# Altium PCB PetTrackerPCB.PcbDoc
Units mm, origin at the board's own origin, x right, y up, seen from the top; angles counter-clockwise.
Board outline 116.71 x 58.42 mm, 4 copper layers (Top Layer, GND Plane, PWR Plane, Bottom Layer), stack 0.868 mm thick; 37 components, 41 nets, 216 pads, 92 vias.
Unrouted connection lines stored in the file: 63.
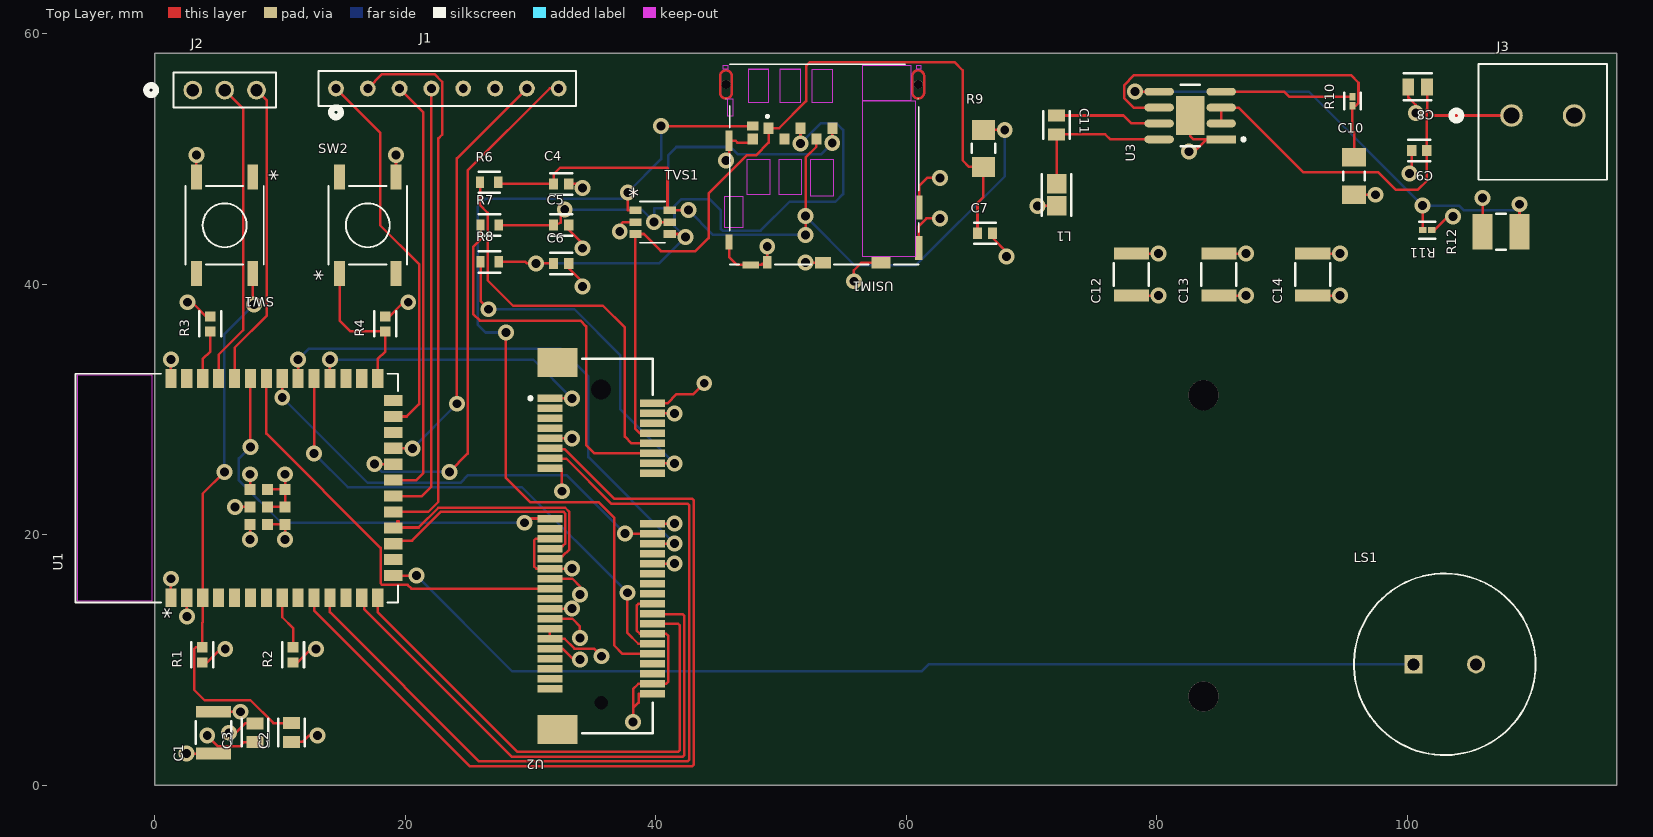
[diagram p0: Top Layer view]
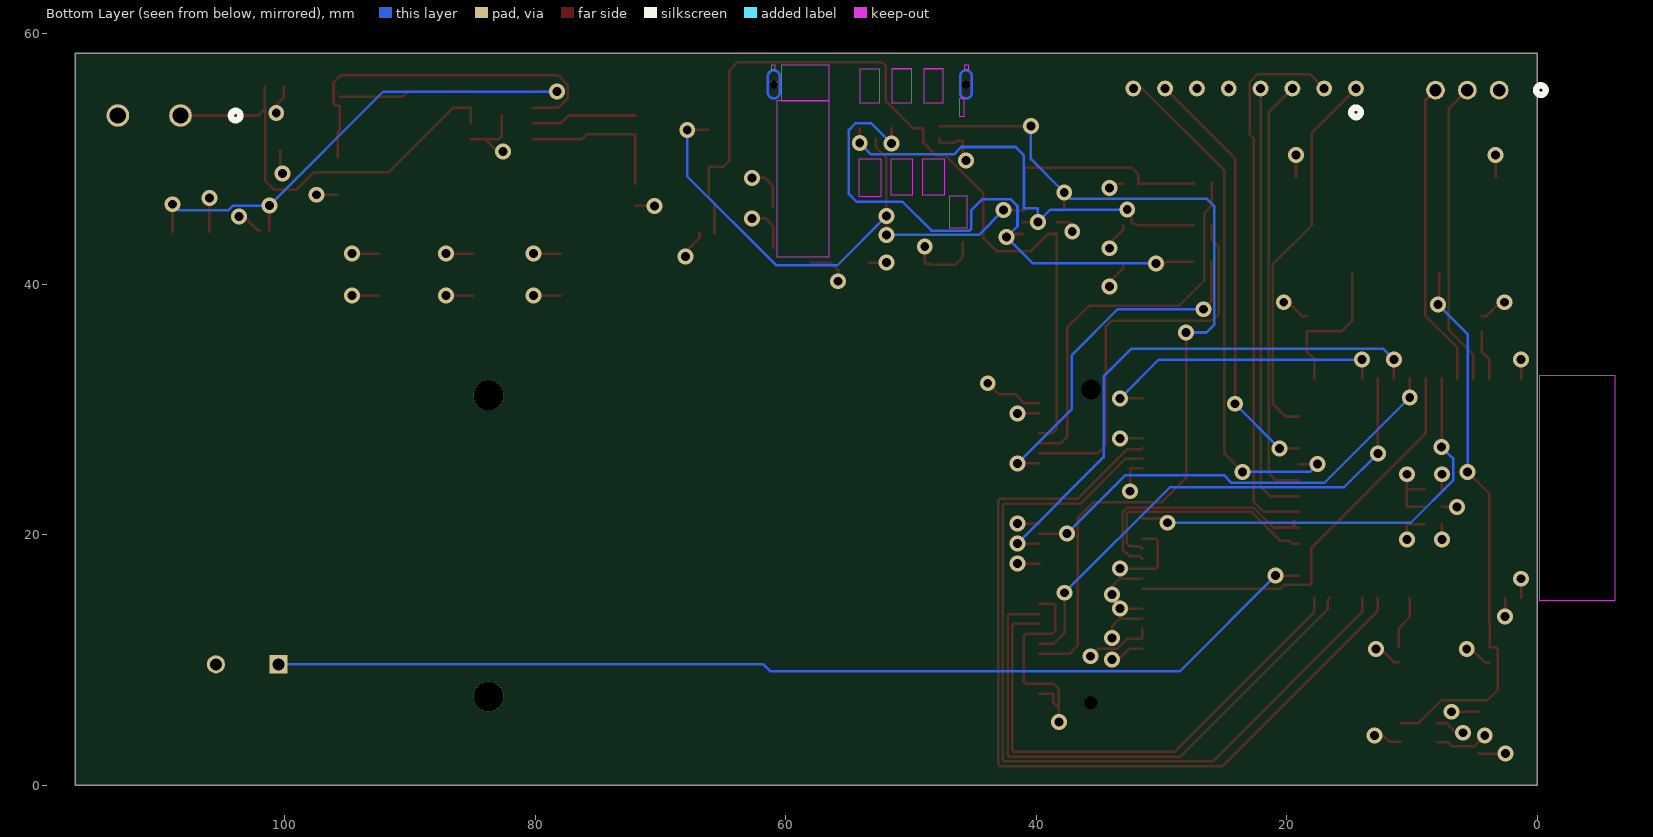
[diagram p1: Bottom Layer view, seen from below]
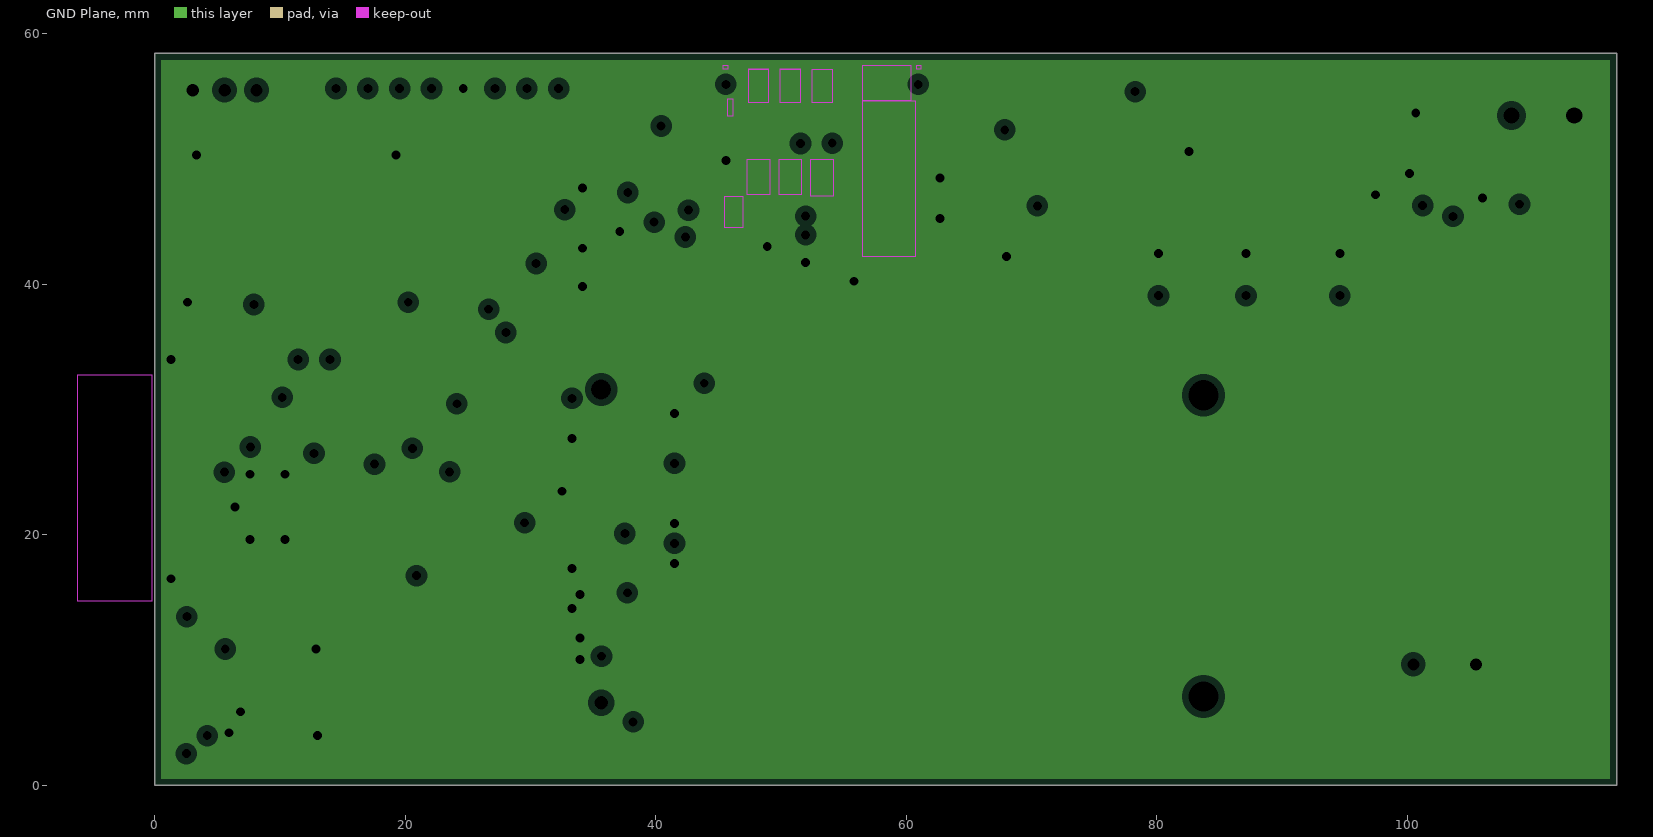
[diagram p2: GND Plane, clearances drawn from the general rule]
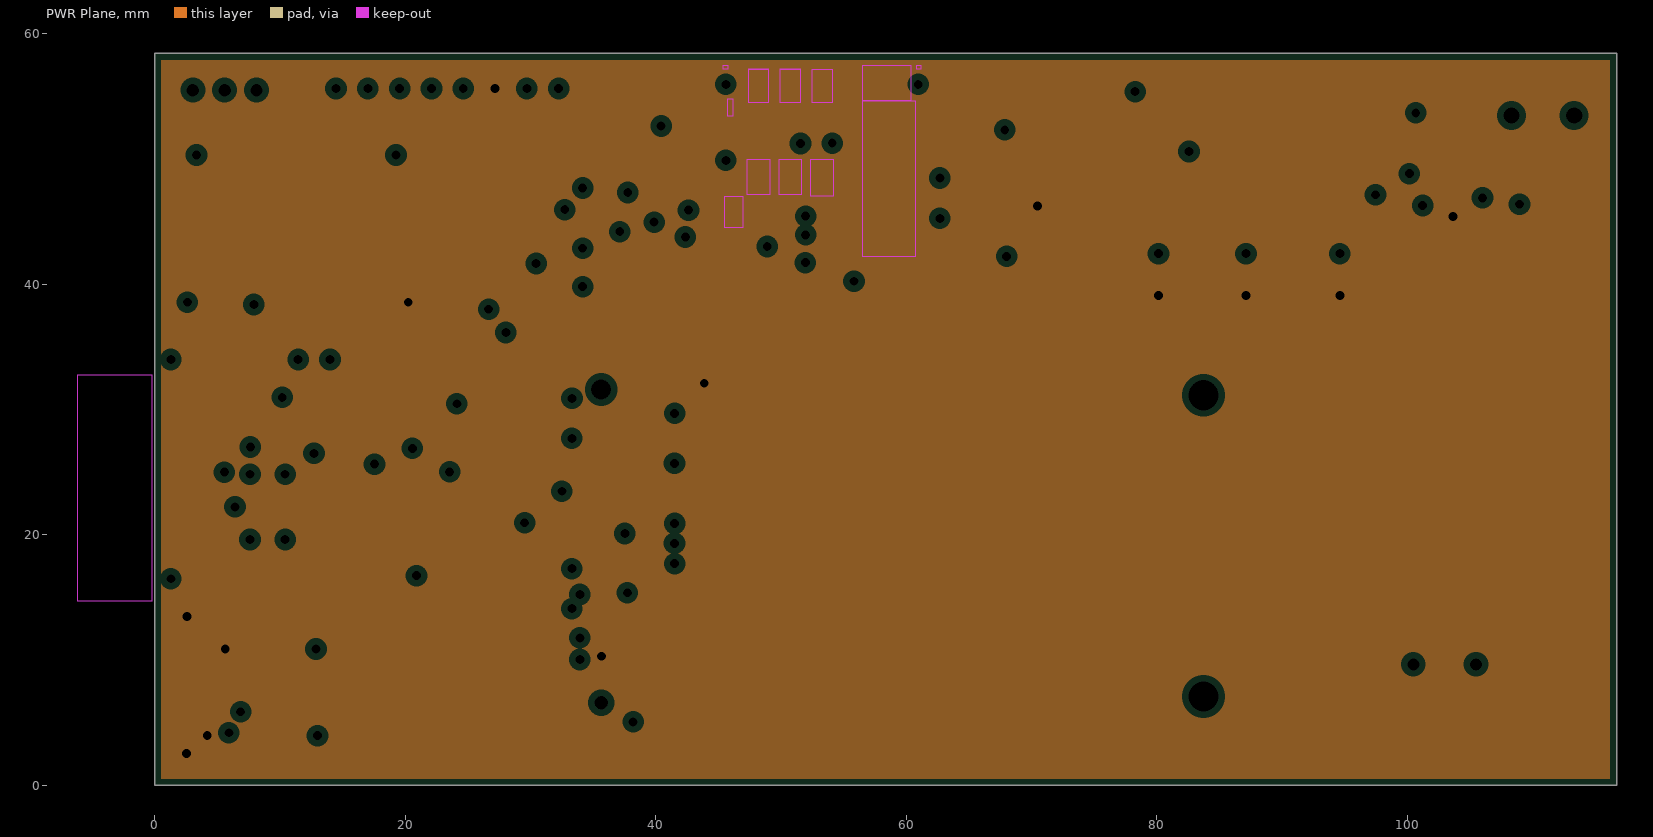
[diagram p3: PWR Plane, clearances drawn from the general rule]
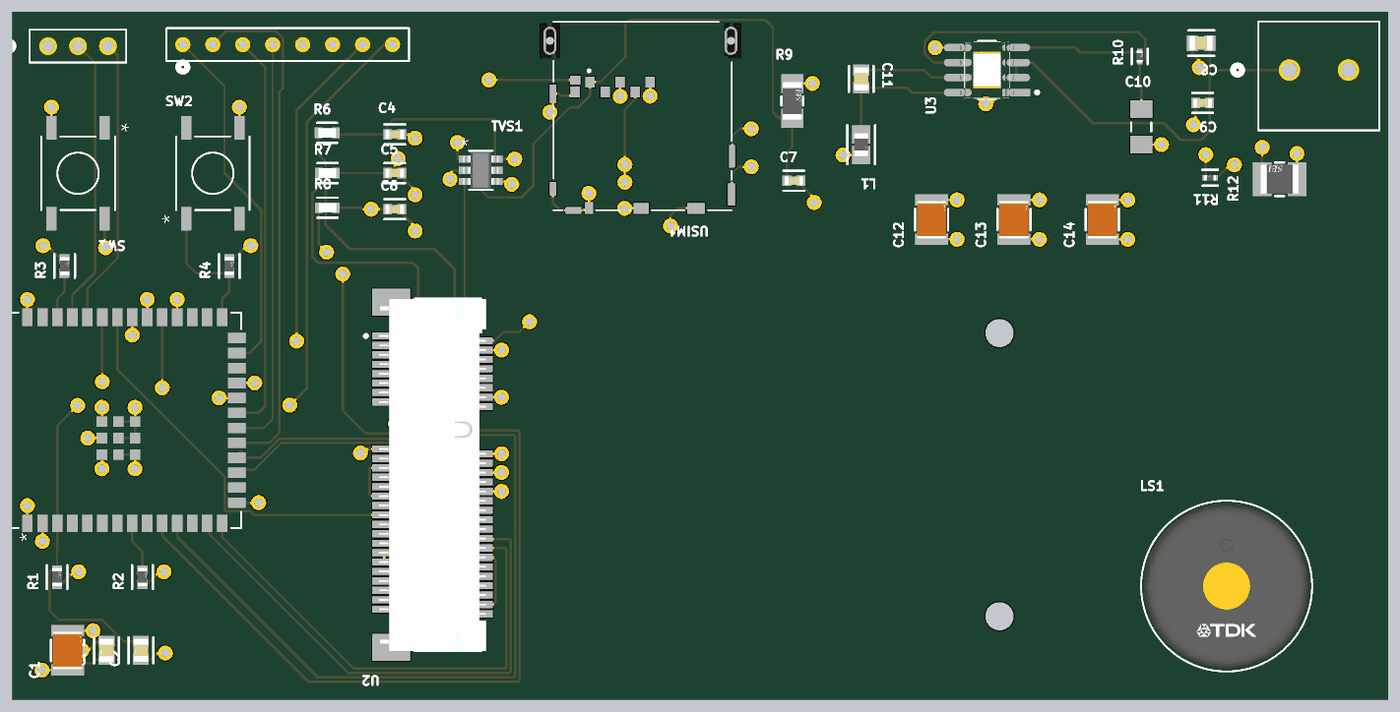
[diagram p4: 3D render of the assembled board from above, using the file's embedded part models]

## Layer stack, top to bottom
Top Solder: solder mask 0.0102, Solder Resist, Dk 3.5
Top Layer: signal copper 0.0356
Dielectric 4: core 0.1016, Core-009, Dk 4.5
Dielectric 2: core 0.1016, Core-009, Dk 4.5
GND Plane: plane copper 0.035, net GND
Dielectric 1: dielectric 0.32, FR-4, Dk 4.8
PWR Plane: plane copper 0.035, net +3V3
Dielectric 3: core 0.1016, Core-009, Dk 4.5
Dielectric 5: core 0.1016, Core-009, Dk 4.5
Bottom Layer: signal copper 0.0356
Bottom Solder: solder mask 0.0102, Solder Resist, Dk 3.5

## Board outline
0,0 116.713,0 116.713,58.42 0,58.42

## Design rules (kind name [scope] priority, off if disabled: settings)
Clearance [All] p1: gap=0.127 ignorepadtopadclearanceinfootprint=FALSE
Height [All] p1 off: minheight=0 maxheight=25.4 prefheight=12.7
PlaneClearance [All] p1: clearance=0.508
PlaneConnect [All] p1: planeconnectstyle=Relief reliefexpansion=0.508 reliefentries=4 reliefconductorwidth=0.254 reliefairgap=0.254
PolygonConnect [All] p1: connectstyle=Relief reliefconductorwidth=0.254 reliefentries=4 polygonreliefangle="90 Angle" airgapwidth=0.254
RoutingVias [All] p1: holewidth=0.711 width=1.27 viastyle="Through Hole" minholewidth=0.711 minwidth=1.27 maxholewidth=0.711 maxwidth=1.27
SolderMaskExpansion [All] p1: expansion=0.102 istentingtop=FALSE
SupplyNets "Schematic Supply Nets_2" [InNet('GND')] p1: voltage=0.000
SupplyNets "Schematic Supply Nets_1" [InNet('Vin')] p2: voltage=0.000
SupplyNets "Schematic Supply Nets" [InNet('+3V3')] p3: voltage=0.000
Width [All] p1: maxlimit=25.4 minlimit=0.127 preferedwidth=0.203
27 further rules are at their usual default settings.

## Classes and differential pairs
component class PowerSupply: C8 C9 C10 C11 C12 C13 C14 CBOOT CHF CIN Cout CVCC J3 L L1 R10 R11 R12 RFBB RFBT U3
component class EC25: C4 C5 C6 C7 CRF1 CRF2 CRF3 CRF4 R6 R7 R8 R9 RDB1 RDB2 RDB3 RS1 TVS1 "TVS Array" U2 USIM1 "USIM Connector"
component class Dataflow: C1 C2 C3 "Camera Interface" J1 J2 LS1 R1 R2 R3 R4 RDB RPU1 S2 SW1 SW2 U1 "USB Connector"

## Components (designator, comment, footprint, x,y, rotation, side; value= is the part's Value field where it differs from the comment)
C1 "22uF" FP-C3225-250-0_4-IPC_B 4.699,4.191 r90 top
C2 "0.1uF" FP-C0805C104M5UACTU-MFG 10.922,4.203 r90 top
C3 "0.1uF" FP-C0805C104M5UACTU-MFG 8.001,4.191 r90 top
C4 "0.1uF" FP-C0603C-CF-MFG 32.447,48.006 r0 top value="0.10 μF"
C5 "0.1uF" FP-C0603C-CF-MFG 32.447,44.72 r0 top value="0.10 μF"
C6 "0.1uF" FP-C0603C-CF-MFG 32.447,41.656 r0 top value="0.10 μF"
C7 "0.1uF" FP-C0603C-CF-MFG 66.294,44.069 r0 top value="0.10 μF"
C8 "10uF" FP-C0805C-DG-MFG 100.838,55.753 r180 top
C9 "0.22uF" FP-C0603C-CF-MFG 100.965,50.673 r180 top value="0.22 μF"
C10 "1uF" CAPC3216X180X50ML20T25 95.758,48.641 r90 top
C11 "0.1uF" FP-C0805C104M5UACTU-MFG 72.009,52.717 r270 top
C12 "22uF" FP-C3225-250-0_4-IPC_B 77.978,40.767 r90 top
C13 "22uF" FP-C3225-250-0_4-IPC_B 84.963,40.767 r90 top
C14 "22uF" FP-C3225-250-0_4-IPC_B 92.456,40.767 r90 top
J1 "TS-108-T-A" CON8_1X8_TU_HTS_SAI 23.368,55.626 r0 top
J2 "PREC003SAAN-RC" CONN_PREC003SAAN-RC_SUL 3.048,55.499 r0 top
J3 "1935161" CONN_1935161_PXC 108.331,53.467 r0 top value=10uF
L1 "6.8uH" FP-MLZ2012-0_85-IPC_A 72.009,47.13 r270 top
LS1 "PS1440P02BT" FP-PS1440P02BT-MFG 102.997,9.652 r0 top
R1 "10kΩ" FP-RMCF0603-IPC_C 3.81,10.414 r90 top
R2 "10kΩ" FP-RMCF0603-IPC_C 11.049,10.414 r90 top
R3 "10kΩ" FP-RMCF0603-IPC_C 4.445,36.83 r90 top
R4 "10kΩ" FP-RMCF0603-IPC_C 18.415,36.83 r90 top
R6 "0Ω" FP-RMCF0603-MFG 26.707,48.133 r0 top value=0mΩ
R7 "0Ω" FP-RMCF0603-MFG 26.744,44.718 r0 top value=0mΩ
R8 "0Ω" FP-RMCF0603-MFG 26.744,41.783 r0 top value=0mΩ
R9 "15kΩ" FP-RMCF1206-IPC_A 66.167,50.848 r90 top
R10 "100kΩ" FP-RMCF0402-IPC_C 95.631,54.61 r90 top
R11 "100kΩ" FP-RMCF0402-IPC_C 101.6,44.323 r180 top
R12 "3.3kΩ" FP-RMCF1210-IPC_A 107.49,44.196 r180 top
SW1 "PTS645SL43SMTR92LFS" PTS645SL43SMTR92LFS_CNK 5.588,44.704 r270 top
SW2 "PTS645SL43SMTR92LFS" PTS645SL43SMTR92LFS_CNK 17.018,44.704 r90 top
TVS1 "AQRV05-4HTG" SOT23-6_LTF 39.751,44.958 r0 top
U1 "ESP32-S2-SOLO-N4R2" MOD41_ESP32-S2-SOLO_EXP 6.557,23.722 r90 top
U2 "2041119-1" TECO-2041119-1_3_V 35.651,19.092 r270 top
U3 "LMR33640ADDAR" FP-DDA0008J-IPC_A 82.677,53.467 r180 top
USIM1 "2174803-2" CONN_2174803-2 50.927,51.151 r180 top

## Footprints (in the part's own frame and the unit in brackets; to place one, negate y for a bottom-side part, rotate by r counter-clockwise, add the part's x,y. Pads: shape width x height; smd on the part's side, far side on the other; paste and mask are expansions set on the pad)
CAPC3216X180X50ML20T25 [mm] "Chip Capacitor, 2-Leads, Body 3.40x1.80mm, IPC Low Density"
  rect 1.5x1.9 smd: 1(-1.5,0) 2(1.5,0)
  silkscreen extent -0.35,-0.85 0.35,0.85, body extent -1.7,-0.9 1.7,0.9, height 1.8
CON8_1X8_TU_HTS_SAI [mil]
  round 50 / inner round 60 / far side round 50 hole 28 paste-99999 mask+0: 1(-350,0) 2(-250,0) 3(-150,0) 4(-50,0) 5(50,0) 6(150,0) 7(250,0) 8(350,0)
  silkscreen extent -405,-90 405,55
CONN_1935161_PXC [mil]
  round 71 / inner round 60 / far side round 71 hole 51 paste-99999 mask+0: 1(0,0) 2(196.85,0)
  silkscreen extent -188,-202 300,162
CONN_2174803-2 [mm]
  rect 0.8x0.9 smd: C1(1.905,-1.3) C2(-0.635,-1.3) C3(-3.175,-1.3) C5(3.175,-0.45) C6(0.635,-0.45) C7(-1.905,-0.45)
  rect 0.1x0.1 smd paste-1 mask+0: C8(5.315,-3.657) C17(-10.035,-3.657)
  rect 0.54x1.6 smd: C9(5.065,-0.3)
  rect 0.54x1.17 smd: C10(5.065,7.785)
  rect 1.33x0.55 smd: C11(3.33,9.605)
  rect 0.7x0.98 smd: C12(2.015,9.39)
  rect 1.3x0.91 smd: C13(-2.435,9.425)
  rect 1.53x0.91 smd: C14(-7.07,9.425)
  rect 0.6x1.9 smd: C15(-10.085,8.25)
  rect 0.5x1.9 smd: C16(-10.135,5.02)
  rect 0.9x0.75 smd: SW(3.175,-1.475)
  round 0.7 hole 0.7 unplated: ""(-10.035,-4.8) ""(5.315,-4.8)
  Top Layer region: 123 vertices and 1 holes, not listed, extent 4.765,-6 5.865,-3.6
  Top Layer region: 124 vertices and 1 holes, not listed, extent -10.585,-6 -9.485,-3.6
  Bottom Layer region: 123 vertices and 1 holes, not listed, extent 4.765,-6 5.865,-3.6
  Bottom Layer region: 124 vertices and 1 holes, not listed, extent -10.585,-6 -9.485,-3.6
  Keep-Out Layer region: -5.624,-3.502 -9.806,-3.502 -9.806,8.97 -5.624,8.97
  Keep-Out Layer region: -5.624,-6.326 -9.458,-6.326 -9.458,-3.5 -5.624,-3.5
  Keep-Out Layer region: -1.565,-6.021 -3.155,-6.021 -3.155,-3.35 -1.565,-3.35
  Keep-Out Layer region: 0.975,-6.024 -0.615,-6.024 -0.615,-3.35 0.975,-3.35
  Keep-Out Layer region: 3.515,-6.031 1.928,-6.031 1.928,-3.35 3.515,-3.35
  Keep-Out Layer region: 5.515,-6.332 5.175,-6.332 5.175,-6.02 5.515,-6.02
  Keep-Out Layer region: 5.165,-3.65 4.765,-3.65 4.765,-2.25 5.165,-2.25
  Keep-Out Layer region: -1.465,1.172 -3.261,1.172 -3.261,4.12 -1.465,4.12
  Keep-Out Layer region: 1.075,1.171 -0.716,1.171 -0.716,4 1.075,4
  Keep-Out Layer region: 3.615,1.172 1.828,1.172 1.828,4 3.615,4
  Keep-Out Layer region: 5.42,4.127 3.977,4.127 3.977,6.63 5.42,6.63
  Keep-Out Layer region: -9.9,-6.323 -10.24,-6.323 -10.24,-6.02 -9.9,-6.02
  Keep-Out Layer region: -5.624,-3.505 -9.815,-3.505 -9.815,8.97 -5.624,8.97
  Keep-Out Layer region: -5.624,-6.322 -9.452,-6.322 -9.452,-3.5 -5.624,-3.5
  Keep-Out Layer region: -1.565,-6.027 -3.159,-6.027 -3.159,-3.35 -1.565,-3.35
  Keep-Out Layer region: 0.975,-6.023 -0.615,-6.023 -0.615,-3.35 0.975,-3.35
  Keep-Out Layer region: 3.515,-6.021 1.925,-6.021 1.925,-3.35 3.515,-3.35
  Keep-Out Layer region: 5.515,-6.326 5.17,-6.326 5.17,-6.02 5.515,-6.02
  Keep-Out Layer region: 5.165,-3.653 4.768,-3.653 4.768,-2.25 5.165,-2.25
  Keep-Out Layer region: -1.465,1.172 -3.261,1.172 -3.261,4.12 -1.465,4.12
  Keep-Out Layer region: 1.075,1.171 -0.716,1.171 -0.716,4 1.075,4
  Keep-Out Layer region: 3.615,1.171 1.826,1.171 1.826,4 3.615,4
  Keep-Out Layer region: 5.42,4.123 3.973,4.123 3.973,6.63 5.42,6.63
  Keep-Out Layer region: -9.9,-6.332 -10.255,-6.332 -10.255,-6.02 -9.9,-6.02
  Keep-Out Layer region: -5.624,-3.506 -9.818,-3.506 -9.818,8.97 -5.624,8.97
  Keep-Out Layer region: -5.624,-6.322 -9.454,-6.322 -9.454,-3.5 -5.624,-3.5
  Keep-Out Layer region: -1.565,-6.024 -3.157,-6.024 -3.157,-3.35 -1.565,-3.35
  Keep-Out Layer region: 0.975,-6.03 -0.616,-6.03 -0.616,-3.35 0.975,-3.35
  Keep-Out Layer region: 3.515,-6.028 1.927,-6.028 1.927,-3.35 3.515,-3.35
  Keep-Out Layer region: 5.515,-6.332 5.175,-6.332 5.175,-6.02 5.515,-6.02
  Keep-Out Layer region: 5.165,-3.653 4.769,-3.653 4.769,-2.25 5.165,-2.25
  Keep-Out Layer region: -1.465,1.172 -3.261,1.172 -3.261,4.12 -1.465,4.12
  Keep-Out Layer region: 1.075,1.171 -0.715,1.171 -0.715,4 1.075,4
  Keep-Out Layer region: 3.615,1.17 1.825,1.17 1.825,4 3.615,4
  Keep-Out Layer region: 5.42,4.121 3.971,4.121 3.971,6.63 5.42,6.63
  Keep-Out Layer region: -9.9,-6.332 -10.255,-6.332 -10.255,-6.02 -9.9,-6.02
  silkscreen extent -10.09,-6.4 5.01,9.58
CONN_PREC003SAAN-RC_SUL [mil]
  round 59 / inner round 60 / far side round 59 hole 39 paste-99999 mask+0: 1(0,0) 2(100,0) 3(200,0)
  silkscreen extent -146,-55 261,55
FP-C0603C-CF-MFG [mm]
  rect 0.75x0.9 smd paste+0 mask+0: 1(-0.6,0) 2(0.6,0)
  silkscreen extent -0.88,-0.85 0.88,0.85, body extent -1.2,-0.6 1.2,0.6, height 0.25
FP-C0805C104M5UACTU-MFG [mm]
  rect 0.95x1.35 smd paste+0 mask+0: 1(-0.75,0) 2(0.75,0)
  silkscreen extent -1.1,-1.05 1.1,1.05, body extent -1.4,-0.85 1.4,0.85, height 0.25
FP-C0805C-DG-MFG [mm]
  rect 0.95x1.35 smd paste+0 mask+0: 1(-0.75,0) 2(0.75,0)
  silkscreen extent -1.11,-1.08 1.1,1.07, body extent -1.4,-0.85 1.4,0.85, height 0.25
FP-C3225-250-0_4-IPC_B [mm]
  rect 0.953x2.804 smd paste+0 mask+0: 1(-1.675,0) 2(1.675,0)
  silkscreen extent -0.9,-1.4 0.9,1.4, body extent -2.4,-1.65 2.4,1.65, height 0.25
FP-DDA0008J-IPC_A [mm]
  rect 2.353x0.622 smd paste+0 mask+0: 1(-2.477,1.905)
  rrect100% 2.353x0.622 smd paste+0 mask+0: 2(-2.477,0.635) 3(-2.477,-0.635) 4(-2.477,-1.905) 5(2.477,-1.905) 6(2.477,-0.635) 7(2.477,0.635) 8(2.477,1.905)
  rect 2.3x3.1 smd paste-1000 mask+0: 9(0,0)
  silkscreen extent -4.38,-2.45 0.75,2.45, body extent -4.15,-2.95 4.15,2.95, height 0.25
FP-MLZ2012-0_85-IPC_A [mm]
  rect 1.554x1.556 smd paste+0 mask+0: 1(-0.876,0) 2(0.876,0)
  silkscreen extent -1.65,-1.18 1.65,1.18, body extent -2.15,-1.28 2.15,1.28, height 0.25
FP-PS1440P02BT-MFG [mm]
  rect 1.45x1.45 hole 0.95 paste-2539.97 mask+0: 1(-2.5,0)
  round 1.45 hole 0.95 paste-2539.97 mask+0: 2(2.5,0)
  silkscreen extent -7.25,-7.25 7.25,7.25, body extent -7.35,-7.35 7.35,7.35, height 0.25
FP-RMCF0402-IPC_C [mm]
  rect 0.581x0.472 smd paste+0 mask+0: 1(-0.366,0) 2(0.366,0)
  silkscreen extent -0.66,-0.67 0.66,0.67, body extent -0.76,-0.38 0.76,0.38, height 0.25
FP-RMCF0603-IPC_C [mm]
  rect 0.806x0.858 smd paste+0 mask+0: 1(-0.601,0) 2(0.601,0)
  silkscreen extent -1,-0.87 1,0.87, body extent -1.1,-0.58 1.1,0.58, height 0.25
FP-RMCF0603-MFG [mm]
  rect 0.65x0.9 smd paste+0 mask+0: 1(-0.725,0) 2(0.725,0)
  silkscreen extent -0.85,-0.85 0.85,0.85, body extent -1.15,-0.58 1.15,0.58, height 0.25
FP-RMCF1206-IPC_A [mm]
  rect 1.604x1.858 smd paste+0 mask+0: 1(-1.476,0) 2(1.476,0)
  silkscreen extent -0.37,-0.93 0.37,0.93, body extent -2.78,-1.43 2.78,1.43, height 0.25
FP-RMCF1210-IPC_A [mm]
  rect 1.604x2.855 smd paste+0 mask+0: 1(-1.476,0) 2(1.476,0)
  silkscreen extent -0.37,-1.43 0.37,1.43, body extent -2.78,-1.93 2.78,1.93, height 0.25
MOD41_ESP32-S2-SOLO_EXP [mil]
  rect 59x35 smd paste+0 mask+0: 1(-344.49,207.09) 2(-344.49,157.09) 3(-344.49,107.09) 4(-344.49,57.09) 5(-344.49,7.09) 6(-344.49,-42.91) 7(-344.49,-92.91) 8(-344.49,-142.91) 9(-344.49,-192.91) 10(-344.49,-242.91) 11(-344.49,-292.91) 12(-344.49,-342.91) 13(-344.49,-392.91) 14(-344.49,-442.91) 27(344.49,-442.91) 28(344.49,-392.91) 29(344.49,-342.91) 30(344.49,-292.91) 31(344.49,-242.91) 32(344.49,-192.91) 33(344.49,-142.91) 34(344.49,-92.91) 35(344.49,-42.91) 36(344.49,7.09) 37(344.49,57.09) 38(344.49,107.09) 39(344.49,157.09) 40(344.49,207.09)
  rect 35x59 smd paste+0 mask+0: 15(-275,-492.13) 16(-225,-492.13) 17(-175,-492.13) 18(-125,-492.13) 19(-75,-492.13) 20(-25,-492.13) 21(25,-492.13) 22(75,-492.13) 23(125,-492.13) 24(175,-492.13) 25(225,-492.13) 26(275,-492.13)
  rect 35x35 smd paste+0 mask+0: 41(-59.05,-96.85) 42(-114.17,-41.73) 43(-114.17,-96.85) 44(-114.17,-151.97) 45(-59.05,-151.97) 46(-3.94,-151.97) 47(-3.94,-96.85) 48(-3.94,-41.73) 49(-59.05,-41.73)
  Keep-Out Layer region: 354.5,502 -354.5,502 -354.5,266 354.5,266
  silkscreen extent -359,-507 360,507
PTS645SL43SMTR92LFS_CNK [mil]
  rect 79x34 smd paste+0 mask+0: 1(-151.5,88.58) 2(151.5,88.58) 3(-151.5,-88.58) 4(151.5,-88.58)
  silkscreen extent -123,-123 123,123
SOT23-6_LTF [mil]
  rect 38.5x24 smd paste+0 mask+0: 1(-53.75,37.4) 2(-53.75,0) 3(-53.75,-37.4) 4(53.75,-37.4) 5(53.75,0) 6(53.75,37.4)
  silkscreen extent -40,-65 40,65, body extent -59,-60 59,60, height 57
TECO-2041119-1_3_V [mm] "Connector, 52-Leads, Body 29.9x8.2mm, Pitch 0.4mm"
  rect 0.6x2 smd: 1(-11.8,-4.1) 2(-11.4,4.1) 3(-11,-4.1) 4(-10.6,4.1) 5(-10.2,-4.1) 6(-9.8,4.1) 7(-9.4,-4.1) 8(-9,4.1) 9(-8.6,-4.1) 10(-8.2,4.1) 11(-7.8,-4.1) 12(-7.4,4.1) 13(-7,-4.1) 14(-6.6,4.1) 15(-6.2,-4.1) 16(-5.8,4.1) 17(-2.2,-4.1) 18(-1.8,4.1) 19(-1.4,-4.1) 20(-1,4.1) 21(-0.6,-4.1) 22(-0.2,4.1) 23(0.2,-4.1) 24(0.6,4.1) 25(1,-4.1) 26(1.4,4.1) 27(1.8,-4.1) 28(2.2,4.1) 29(2.6,-4.1) 30(3,4.1) 31(3.4,-4.1) 32(3.8,4.1) 33(4.2,-4.1) 34(4.6,4.1) 35(5,-4.1) 36(5.4,4.1) 37(5.8,-4.1) 38(6.2,4.1) 39(6.6,-4.1) 40(7,4.1) 41(7.4,-4.1) 42(7.8,4.1) 43(8.2,-4.1) 44(8.6,4.1) 45(9,-4.1) 46(9.4,4.1) 47(9.8,-4.1) 48(10.2,4.1) 49(10.6,-4.1) 50(11,4.1) 51(11.4,-4.1) 52(11.8,4.1)
  round 1.3 hole 1.6 unplated: MH1(-12.5,0)
  round 0.9 hole 1.1 unplated: MH2(12.5,0)
  rect 2.3x3.2 smd: MP1(-14.65,-3.5) MP2(14.65,-3.5)
  silkscreen extent -14.95,-5.77 14.95,4.1, body extent -14.95,-4.54 14.95,4.55, height 4

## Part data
C1 C12 C13 C14: library part CMP-2000-06052-2, "C3225X7R1C226M250AC Multilayer Ceramic Capacitors 22uF ±20% 16V X7R SMD 1210", Case Code (Imperial)=1210, Case Code (Metric)=3225, Dielectric=X7R, Dielectric Material=Ceramic, Max Operating Temperature=125°C, Min Operating Temperature=-55°C, Package Quantity=1, Tolerance=20%, Voltage Rating=16V
C2 C3 C11: library part CMP-2007-03742-2, "C0805C104M5UACTU CAP CER 0.1UF 50V Z5U 0805", Capacitance=100nF, Case Code (Imperial)=0805, Case Code (Metric)=2012, Dielectric=Z5U, Dielectric Material=Ceramic, Max Operating Temperature=85°C, Min Operating Temperature=10°C, Package Quantity=1, Tolerance=20%, Voltage=50V
C4 C5 C6 C7: library part CMP-2006-03056-2, "C0603C104J5RACTU CAP CER 0.1UF 50V 5% X7R 0603", Capacitance="0.10 μF", Manufacturer=KEMET, Manufacturer Part Number=C0603C104J5RACTU, Package=C0603C-CF, Temperature="-55°C to +125°C", Temperature Characteristic=X7R, Temperature Coefficient=30ppm/°C, Temperature Range High=+125°C, Temperature Range Low=-55°C, Tolerance=0.05, Voltage Rating="50 V"
C8: library part CMP-2007-03243-2, "C0805C106K8PACTU CAP CER 10UF 10V X5R 0805", 3DS Part Number=220-00001, Manufacturer=Kemet, Manufacturer Part Number=C0805C106K8PACTU, Package=C0805C-DG, Temperature="-55°C to +85°C", Temperature Characteristic=X5R, Temperature Coefficient=15%, Temperature Range High=+85°C, Temperature Range Low=-55°C, Tolerance=10%, Voltage=10V
C9: library part CMP-2006-03146-2, "C0603C224K3RACTU CAP CER 0.22UF 25V 10% X7R 0603", Capacitance="0.22 μF", Manufacturer=KEMET, Manufacturer Part Number=C0603C224K3RACTU, Package=C0603C-CF, Temperature="-55°C to +125°C", Temperature Characteristic=X7R, Temperature Coefficient=30ppm/°C, Temperature Range High=+125°C, Temperature Range Low=-55°C, Tolerance=0.1, Voltage Rating="25 V"
C10: library part CMP-2000-04991-1, "C1206C105K3RACTU Chip Capacitor, 1 uF, +/- 10%, 25 V, -55 to 125 degC, 1206 (3216 Metric), RoHS, Tape and Reel", Capacitance - nF=1000nF, Case Code - in=1206, Case Code - mm=3216, Case Height=1.6mm, Case Length=3.2mm, Dielectric=X7R, Manufacturer=Kemet, Maximum Operating Temperature=+125C, Minimum Operating Temperature=-55C, Operating Temperature Range=-55Cto+125C, Package / Case=1206(3216metric), Package Description="2-Pin Surface Mount Device, Body 3.2 x 1.6 mm", Temperature Coefficient / Code=+/-15%, Tolerance=10%, Voltage Rating=25V
J1: "No Description Available", Mfr_Name="Samtec Inc"
J2: "No Description Available", Mfr_Name=Sullins
J3: "Ceramic Capacitor, Multilayer, Ceramic, 16V, 10% +Tol, 10% -Tol, X5R, 15% TC, 10uF, Surface Mount, 0805", Capacitor Type=Ceramic, Case/Package=0805, Manufacturer=Samsung, Manufacturer Part Number=CL21A106KOQNNNE, Max Operating Temperature=85°C, Mfr_Name="Phoenix Contact", Min Operating Temperature=-55°C, Package Shape=Rectangular, Package Style=SMTMeter, Rated DC Voltage (URdc)=16V, Supplier Part Number=1276-1096-1-ND, Temperature Characteristics Code=X5R, Tolerance  (fill in as +-)=10%
L1: library part CMP-08253-000092-1, "MLZ2012N6R8LT000 Shielded Multilayer Inductor 6.8uH ±20% 550mA 325mΩ SMD 0805", Case Code (Imperial)=0805, Case Code (Metric)=2012, Current Rating=550mA, DC Resistance (DCR)=250mR, Max Operating Temperature=125°C, Min Operating Temperature=-55°C, Package Quantity=1, Saturation Current=110mA, Self Resonant Frequency=60MHz, Test Frequency=2MHz, Tolerance=20%
LS1: library part CMP-08413-000003-1, "AUDIO PIEZO TRANSDUCER 30V TH", Frequency=4kHz, Max Operating Temperature=70°C, Min Operating Temperature=-10°C, Operating Supply Voltage=3V, Package Quantity=350
R1 R2 R3 R4: library part CMP-26527-002098-1, "RMCF0603JT10K0 10kΩ ±5% 0.1W 0603 Thick Film Chip Resistor AEC-Q200 compliant", Case Code (Imperial)=0603, Case Code (Metric)=1608, Max Operating Temperature=155°C, Max Power Dissipation=100mW, Min Operating Temperature=-55°C, Resistance=10kR, Resistor Type="Thick Film", Temperature Coefficient=100ppm/°C, Tolerance=5%
R6 R7 R8: library part CMP-26527-000011-1, "RMCF0603ZT0R00 RES 0 OHM JUMPER 1/10W 0603", Manufacturer=Stackpole, Manufacturer Part Number=RMCF0603ZT0R00, Package=RMCF0603, Power Rating=0.1W, Resistance=0mΩ, Temperature="-55°C to +155°C", Temperature Range High=+155°C, Temperature Range Low=-55°C, Voltage Rating=75V
R9: library part CMP-26527-001400-1, "RMCF1206JT15K0 15kΩ ±5% 0.25W 1206 Thick Film Chip Resistor AEC-Q200 compliant", Case Code (Imperial)=1206, Case Code (Metric)=3216, Max Operating Temperature=155°C, Max Power Dissipation=250mW, Min Operating Temperature=-55°C, Resistance=15kR, Resistor Type="Thick Film", Temperature Coefficient=200ppm/°C, Tolerance=5%
R10 R11: library part CMP-2000-06984-2, "RMCF0402FT100K 100kΩ ±1% 0.063W 0402 Thick Film Chip Resistor AEC-Q200 compliant", Case Code (Imperial)=0402, Case Code (Metric)=1005, Max Operating Temperature=155°C, Max Power Dissipation=63mW, Min Operating Temperature=-55°C, Power Rating=62.5mW, Resistance=100kR, Resistor Type="Thick Film", Temperature Coefficient=100ppm/°C, Tolerance=1%
R12: library part CMP-26527-001928-1, "RMCF1210JT3K30 3.3kΩ ±5% 0.5W 1210 Thick Film Chip Resistor AEC-Q200 compliant", Case/Package=1210, Max Operating Temperature=155°C, Max Power Dissipation=333mW, Min Operating Temperature=-55°C, Resistance=3.3kR, Resistor Type="Thick Film", Temperature Coefficient=200ppm/°C, Tolerance=5%
SW1 SW2: "No Description Available", Mfr_Name="C&K Components"
TVS1: "No Description Available", Mfr_Name="Littelfuse Inc"
U1: "No Description Available", Mfr_Name="Espressif Systems"
U2: library part CMP-2011-00000-2, "mSATA & PCI Express Mini Card Connector, Pitch 0.4 mm, 52 Position, Height 4 mm, RoHS, Tape and Reel", Case\Package=SMD, Housing Colour=Black, Manufacturer="TE Connectivity", Package Description="mSATA & PCI Express Mini Card Connector, Pitch 0.4 mm, 52 Position, Height 4 mm", Package Reference=2041119-1_3
U3: library part CMP-04918-000399-1, "36V 4A 400KHZ REGULATOR"
USIM1: "CONNECTOR, SIM SOCKET, 6POS, 2.54MM; Connector Type:SIM Socket; Series:2174803;", Package=None, Voltage_Rating="10 VAC"

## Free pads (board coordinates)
  round 2.4 hole 2.4 unplated: 2(83.737,31.136) 3(83.737,7.091)

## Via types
v1: diameter 1.27, hole 0.711, Top Layer to Bottom Layer, 92 vias

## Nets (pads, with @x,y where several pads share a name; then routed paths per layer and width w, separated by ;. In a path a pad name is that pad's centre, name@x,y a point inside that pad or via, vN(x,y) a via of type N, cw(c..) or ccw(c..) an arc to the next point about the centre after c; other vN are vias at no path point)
+3V3: C1.1 C3.1 C12.1 C13.1 C14.1 J1.6 L1.2 R1.1 R4.2 R11.1 U1.2 U2.2 U2.39 U2.41 U2.52 | length 36.6
  Top Layer w0.203: v1(2.535,2.516) C1.1 ; v1(2.567,13.461) U1.2 ; R1.1 4.183,9.813 5.241,10.871 v1(5.64,10.871) ; v1(4.198,3.962) 5.061,3.099 6.804,3.099 7.146,3.441 C3.1 ; R4.2 18.754,37.431 19.88,38.557 v1(20.245,38.557) ; U2.39 31.547,12.492 31.547,11.692 U2.41 32.731,11.692 33.518,10.904 35.07,10.904 v1(35.679,10.295) ; v1(38.202,5.055) 38.202,6.172 38.633,6.604 38.633,7.292 U2.52 ; U2.2 40.931,30.492 41.669,31.231 43.016,31.231 v1(43.879,32.094) ; v1(70.469,46.254) L1.2 ; C12.1 v1(80.142,39.092) ; C13.1 v1(87.127,39.092) ; C14.1 v1(94.62,39.092) ; R11.1 102.183,44.323 103.275,45.415 v1(103.657,45.415)
GND: C1.2 C2.1 C3.2 C4.2 C5.2 C6.2 C7.2 C8.2 C9.2 C10.1 C12.2 C13.2 C14.2 J1.5 J2.1 J3.2 LS1.2 R2.1 R3.2 R12.2 SW1.3 SW2.4 TVS1.2 U1.1 U1.40 U1.41 U1.42 U1.43 U1.44 U1.45 U1.46 U1.47 U1.48 U1.49 U2.4 U2.9 U2.15 U2.18 U2.21 U2.26 U2.27 U2.29 U2.34 U2.35 U2.37 U2.40 U2.43 U2.50 U3.1 U3.9 USIM1.C5 USIM1.C8 USIM1.C9 USIM1.C10 USIM1.C11 USIM1.C12 USIM1.C13 USIM1.C14 USIM1.C15 USIM1.C16 USIM1.C17 | length 125.8
  Top Layer w0.203: U1.1 v1(1.297,16.483) ; U1.40 v1(1.297,33.983) ; v1(2.615,38.557) 2.98,38.557 4.106,37.431 R3.2 ; SW1.3 v1(3.338,50.317) ; C1.2 v1(6.863,5.866) ; v1(5.925,4.191) 6.478,4.191 7.228,4.941 C3.2 ; v1(6.411,22.222) U1.49 ; v1(7.617,19.616) U1.42 ; U1.48 v1(7.617,24.828) ; U1.43 U1.44 v1(10.417,19.616) ; U1.41 U1.45 10.439,22.244 10.439,23.6 U1.46 ; U1.47 U1.46 ; v1(10.417,24.828) U1.46 ; C2.1 11.815,3.453 12.324,3.962 v1(12.998,3.962) ; R2.1 11.422,9.813 12.48,10.871 v1(12.879,10.871) ; SW2.4 v1(19.268,50.317) ; U2.43 32.598,10.892 33.45,10.041 v1(33.952,10.041) ; U2.37 33.341,13.292 33.952,12.681 v1(33.952,11.768) ; U2.35 v1(33.313,14.092) ; U2.29 33.341,16.492 33.952,15.881 v1(33.952,15.222) ; U2.21 30.436,19.692 30.302,19.558 30.302,17.47 30.48,17.292 U2.27 v1(33.313,17.292) ; U2.15 32.512,25.292 v1(32.512,23.47) ; U2.9 v1(33.313,27.692) ; C6.2 33.047,41.297 34.174,40.17 v1(34.174,39.805) ; C5.2 33.047,44.361 34.174,43.234 v1(34.174,42.869) ; C4.2 33.847,48.006 v1(34.174,47.679) ; v1(37.135,44.196) 37.135,44.704 37.389,44.958 TVS1.2 ; v1(38.202,5.055) 38.202,7.686 38.608,8.092 U2.50 40.833,8.092 40.996,8.255 40.996,11.938 40.842,12.092 U2.40 38.733,12.092 38.506,12.319 38.506,14.351 38.647,14.492 U2.34 ; U2.26 v1(41.513,17.692) ; U2.18 v1(41.513,20.892) ; U2.4 v1(41.513,29.692) ; v1(45.608,49.889) 45.862,50.143 USIM1.C9 46.375,51.451 46.53,51.296 47.752,51.296 USIM1.C5 ; USIM1.C10 45.862,42.164 46.48,41.546 USIM1.C11 48.438,41.546 48.522,41.631 48.912,41.631 USIM1.C12 v1(48.912,43.013) ; v1(51.95,41.726) USIM1.C13 ; v1(55.831,40.234) 55.831,41.115 56.442,41.726 USIM1.C14 ; USIM1.C15 61.012,44.641 61.623,45.252 v1(62.687,45.252) ; USIM1.C16 61.062,47.871 61.673,48.482 v1(62.687,48.482) ; C7.2 66.894,43.71 68.021,42.583 v1(68.021,42.218) ; C12.2 v1(80.142,42.442) ; v1(82.576,50.597) 83.022,50.597 U3.1@83.987,51.562 ; U3.9 82.677,51.816 82.931,51.562 U3.1@83.987,51.562 ; C13.2 v1(87.127,42.442) ; U3.1 U3.1@83.987,51.562 ; C14.2 v1(94.62,42.442) ; C10.1 v1(97.47,47.141) ; C8.2 100.088,54.904 100.686,54.306 v1(100.686,53.677) ; v1(100.178,48.822) 100.365,49.009 C9.2 ; R12.2 v1(106.015,46.894)
GSM_DTR: U1.34 U2.31 | length 33.8
  Top Layer w0.203: U1.34 8.917,28.067 18.034,18.95 18.034,16.129 18.161,16.002 20.193,16.002 20.503,15.692 U2.31
GSM_LED_WWAN#: U1.31 U2.42 | length 41.2
  Top Layer w0.203: v1(12.727,26.492) U1.31 ; v1(37.743,15.369) 37.743,12.157 38.608,11.292 U2.42
  Bottom Layer w0.203: v1(12.727,26.492) 15.415,23.804 29.307,23.804 v1(37.743,15.369)
GSM_PERST#: U1.32 U2.22 | length 43.9
  Top Layer w0.203: U1.32 v1(11.457,33.985) ; U2.22 41.492,19.292 v1(41.504,19.304)
  Bottom Layer w0.203: v1(11.457,33.985) 12.321,34.849 32.41,34.849 34.62,32.639 34.62,26.187 v1(41.504,19.304)
GSM_RI: U1.35 U2.17 | length 34.9
  Top Layer w0.203: v1(7.647,27) U1.35 ; v1(29.54,20.955) 29.877,21.292 U2.17
  Bottom Layer w0.203: v1(7.647,27) 6.731,26.084 6.731,24.333 10.109,20.955 v1(29.54,20.955)
GSM_W_DISABLE#: U1.33 U2.20 | length 36.1
  Top Layer w0.203: v1(10.185,30.963) 10.187,30.964 U1.33 ; v1(37.541,20.092) U2.20
  Bottom Layer w0.203: v1(10.185,30.963) 17.013,24.135 24.405,24.135 25.034,24.763 32.87,24.763 v1(37.541,20.092)
GSM_WAKE#: U1.30 U2.1 | length 23.9
  Top Layer w0.203: U1.30 v1(13.997,33.985) ; U2.1 33.319,30.892 v1(33.325,30.886)
  Bottom Layer w0.203: v1(13.997,33.985) 30.226,33.985 v1(33.325,30.886)
MCU_CTS: U1.18 U2.25 | length 20.7
  Top Layer w0.203: U1.18 19.355,20.547 19.355,21.082 19.482,21.082 19.482,20.704 19.612,20.574 21.082,20.574 22.659,22.151 32.782,22.151 33.11,21.823 33.11,18.828 32.573,18.29 31.749,18.29 U2.25
MCU_RTS: U1.17 U2.23 | length 18.6
  Top Layer w0.203: U1.17 19.585,19.277 19.839,19.531 20.547,19.531 22.837,21.821 32.646,21.821 32.78,21.687 32.78,19.297 32.573,19.09 31.749,19.09 U2.23
MCU_RXD: U1.11 U2.13 | length 67.8
  Top Layer w0.203: U1.11 13.997,13.816 25.908,1.905 42.553,1.905 42.672,2.024 42.672,22.36 42.553,22.479 36.449,22.479 32.864,26.064 31.579,26.064 U2.13
MCU_TXD: U1.10 U2.11 | length 70.9
  Top Layer w0.203: U1.10@12.727,14.961 12.727,13.943 25.146,1.524 42.934,1.524 43.053,1.643 43.053,22.741 42.934,22.86 36.703,22.86 32.737,26.826 31.617,26.826 U2.11
NetC2_2: C2.2 R1.2 SW1.2 U1.3 | length 44.4
  Top Layer w0.203: v1(5.563,24.994) 3.837,23.268 U1.3 3.837,13.006 3.81,12.979 R1.2 3.302,11.015 3.15,10.863 3.15,7.62 3.988,6.782 7.645,6.782 9.474,4.953 C2.2 ; SW1.2 7.838,38.466 v1(7.925,38.379)
  Bottom Layer w0.203: v1(5.563,24.994) 5.563,36.017 v1(7.925,38.379)
NetC4_1: C4.1 R6.2 R9.2 TVS1.6 USIM1.C7 | length 63.7
  Top Layer w0.203: R6.2 27.432,48.006 C4.1 31.847,48.768 32.376,49.297 40.924,49.297 40.945,49.276 40.945,45.908 TVS1.6 v1(42.621,45.908) ; v1(51.968,43.942) v1(51.968,45.432) 51.968,50.108 52.832,50.971 USIM1.C7 ; R9.2 v1(67.869,52.324)
  Bottom Layer w0.203: v1(42.621,45.908) 44.587,43.942 v1(51.968,43.942) ; v1(51.968,45.432) 55.897,41.504 60.757,41.504 67.869,48.616 v1(67.869,52.324)
NetC5_1: C5.1 R7.2 TVS1.5 USIM1.C3 | length 36.6
  Top Layer w0.203: R7.2 29.642,44.718 29.643,44.72 C5.1 32.436,44.898 32.436,45.644 v1(32.741,45.949) ; v1(39.878,44.958) TVS1.5 ; v1(54.102,51.257) USIM1.C3
  Bottom Layer w0.203: v1(32.741,45.949) 38.887,45.949 v1(39.878,44.958) 39.878,46.076 40.996,46.076 40.996,50.292 41.656,50.952 45.996,50.952 46.581,50.368 53.213,50.368 v1(54.102,51.257)
NetC6_1: C6.1 R8.2 TVS1.4 USIM1.C2 | length 48.8
  Top Layer w0.203: R8.2 29.591,41.783 29.718,41.656 v1(30.455,41.656) C6.1 ; TVS1.4 42.123,44.008 v1(42.367,43.764) ; v1(51.562,51.232) USIM1.C2
  Bottom Layer w0.203: v1(30.455,41.656) 40.259,41.656 v1(42.367,43.764) 41.504,44.628 41.504,46.228 42.062,46.787 44.298,46.787 45.212,45.872 45.212,44.399 45.339,44.272 48.387,44.272 50.698,46.584 54.356,46.584 54.966,47.193 54.966,52.324 54.458,52.832 53.162,52.832 v1(51.562,51.232)
NetC7_1: C7.1 R9.1 TVS1.3 U2.8 USIM1.C1 | length 69.3
  Top Layer w0.203: U2.8 38.735,28.092 38.379,28.448 38.379,44.008 TVS1.3 39.054,44.008 40.426,42.636 43.172,42.636 44.221,43.686 44.221,47.244 47.269,50.292 48.006,50.292 49.022,51.308 USIM1.C1 49.86,52.451 52.019,54.61 52.019,57.429 52.324,57.734 63.856,57.734 64.516,57.074 64.516,49.881 65.024,49.373 R9.1 66.167,46.955 65.694,46.482 C7.1
NetC10_2: C10.2 R10.1 U3.6 | length 29.8
  Top Layer w0.203: U3.6 78.156,54.102 77.394,54.864 77.394,55.88 78.207,56.693 95.504,56.693 96.114,56.083 96.114,54.473 95.885,54.244 R10.1 95.631,52.248 95.758,52.121 C10.2
NetC11_1: C11.1 U3.7 | length 8.5
  Top Layer w0.203: C11.1 77.343,53.467 77.978,52.832 U3.7
NetC11_2: C11.2 L1.1 U3.8 | length 12.3
  Top Layer w0.203: L1.1 C11.2 75.895,51.967 76.3,51.562 U3.8
NetJ1_1: J1.1 U1.25 | length 30.4
  Top Layer w0.203: J1.1 18.009,52.095 18.009,44.704 21.109,41.604 21.109,30.427 20.118,29.437 U1.25
NetJ1_2: J1.2 U1.19 | length 44.3
  Top Layer w0.203: J1.2 18.161,56.769 22.352,56.769 22.962,56.159 22.962,51.943 22.657,51.638 22.657,22.631 21.842,21.817 U1.19
NetJ1_3: J1.3 U1.21 | length 34.1
  Top Layer w0.203: U1.21 20.903,24.357 21.439,24.893 21.439,53.745 J1.3
NetJ1_4: J1.4 U1.20 | length 35.1
  Top Layer w0.203: U1.20 21.336,23.087 22.098,23.849 J1.4
NetJ1_7: J1.7 U1.23 | length 34
  Top Layer w0.203: U1.23 v1(20.574,26.897) ; v1(24.13,30.453) 24.13,50.038 J1.7
  Bottom Layer w0.203: v1(20.574,26.897) v1(24.13,30.453)
NetJ1_8: J1.8 U1.22 | length 42.4
  Top Layer w0.203: v1(17.551,25.629) 17.553,25.627 U1.22 ; v1(23.546,25.019) 24.994,26.467 24.994,49.074 31.546,55.626 J1.8
  Bottom Layer w0.203: v1(17.551,25.629) 18.161,25.019 v1(23.546,25.019)
NetJ2_2: J2.2 U1.37 | length 24.4
  Top Layer w0.203: U1.37 5.107,34.368 7.061,36.322 7.061,54.026 J2.2
NetJ2_3: J2.3 U1.36 | length 24.4
  Top Layer w0.203: U1.36 6.377,34.925 8.956,37.504 8.956,54.671 J2.3
NetLS1_1: LS1.1 U1.15 | length 84.8
  Top Layer w0.203: U1.15 v1(20.904,16.737)
  Bottom Layer w0.203: v1(20.904,16.737) 28.548,9.093 61.239,9.093 61.798,9.652 LS1.1
NetR2_2: R2.2 U1.8 | length 4.3
  Top Layer w0.203: U1.8 10.187,13.41 11.049,12.548 R2.2
NetR3_1: R3.1 U1.38 | length 4
  Top Layer w0.203: U1.38 3.837,34.036 4.445,34.644 R3.1
NetR4_1: R4.1 SW2.1 U1.27 | length 11.8
  Top Layer w0.203: SW2.1 14.768,37.084 15.623,36.229 R4.1 18.415,34.644 17.807,34.036 U1.27
NetR6_1: R6.1 U2.10 | length 31.7
  Top Layer w0.203: R6.1 25.982,46.306 26.594,45.695 26.594,40.31 28.626,38.278 35.789,38.278 37.541,36.525 37.541,27.838 38.088,27.292 U2.10
NetR7_1: R7.1 U2.12 | length 31.8
  Top Layer w0.203: R7.1 26.019,43.57 25.451,43.002 25.451,37.592 25.959,37.084 33.985,37.084 34.442,36.627 34.442,27.152 35.103,26.492 U2.12
NetR8_1: R8.1 U2.14 | length 28.3
  Top Layer w0.203: R8.1 26.019,38.649 v1(26.67,37.998) ; U2.14 v1(41.504,25.692)
  Bottom Layer w0.203: v1(26.67,37.998) 33.503,37.998 37.186,34.315 37.186,30.01 v1(41.504,25.692)
NetR10_2: R10.2 U3.4 | length 10.6
  Top Layer w0.203: U3.4 90.17,55.372 90.566,54.976 R10.2
NetR11_2: R11.2 R12.1 U3.5 | length 40.9
  Top Layer w0.203: v1(78.283,55.372) U3.5 ; R11.2 v1(101.234,46.279) ; R12.1 v1(108.966,46.38)
  Bottom Layer w0.203: v1(78.283,55.372) 92.141,55.372 v1(101.234,46.279) 104.14,46.279 104.521,45.898 108.483,45.898 v1(108.966,46.38)
NetTVS1_1: TVS1.1 U2.44 USIM1.SW | length 75.2
  Top Layer w0.203: v1(28.042,36.144) 28.042,24.536 29.972,22.606 35.433,22.606 36.678,21.361 36.678,11.176 37.362,10.492 U2.44 ; v1(37.77,47.32) 37.77,45.908 TVS1.1 ; v1(40.437,52.626) USIM1.SW
  Bottom Layer w0.203: v1(28.042,36.144) 26.416,36.144 25.806,36.754 25.806,46.228 26.391,46.812 37.262,46.812 v1(37.77,47.32) 40.437,49.987 v1(40.437,52.626)
USB_DM: U1.13 U2.36 | length 45.2
  Top Layer w0.203: U1.13 16.751,14.758 16.751,14.037 28.502,2.286 42.172,2.286 42.291,2.405 42.291,13.522 42.172,13.641 39.802,13.641 U2.36
USB_DP: U1.14 U2.38 | length 42.1
  Top Layer w0.203: U1.14 17.807,13.837 28.977,2.667 41.791,2.667 41.91,2.786 41.91,12.773 41.791,12.892 U2.38
Vin: C8.1 C9.1 J3.1 U3.2 U3.3 | length 35.2
  Top Layer w0.203: U3.2 U3.3 86.538,54.102 91.694,48.946 97.681,48.946 99.078,47.549 100.854,47.549 101.565,48.26 C9.1 101.565,53.964 101.588,53.987 ; C8.1 101.588,53.987 ; J3.1 102.108,53.467 101.588,53.987
pads on no net: SW1.1 SW1.4 SW2.2 SW2.3 U1.4 U1.5 U1.6 U1.7 U1.9 U1.12 U1.16 U1.24 U1.26 U1.28 U1.29 U1.39 U2.3 U2.5 U2.6 U2.7 U2.16 U2.19 U2.24 U2.28 U2.30 U2.32 U2.33 U2.45 U2.46 U2.47 U2.48 U2.49 U2.51 U2.MH1 U2.MH2 U2.MP1 U2.MP2 USIM1. USIM1.C6

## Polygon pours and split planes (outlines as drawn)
GND on GND Plane (split plane): 116.203,0.51 0.51,0.51 0.51,57.91 116.203,57.91
+3V3 on PWR Plane (split plane): 116.203,0.51 0.51,0.51 0.51,57.91 116.203,57.91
